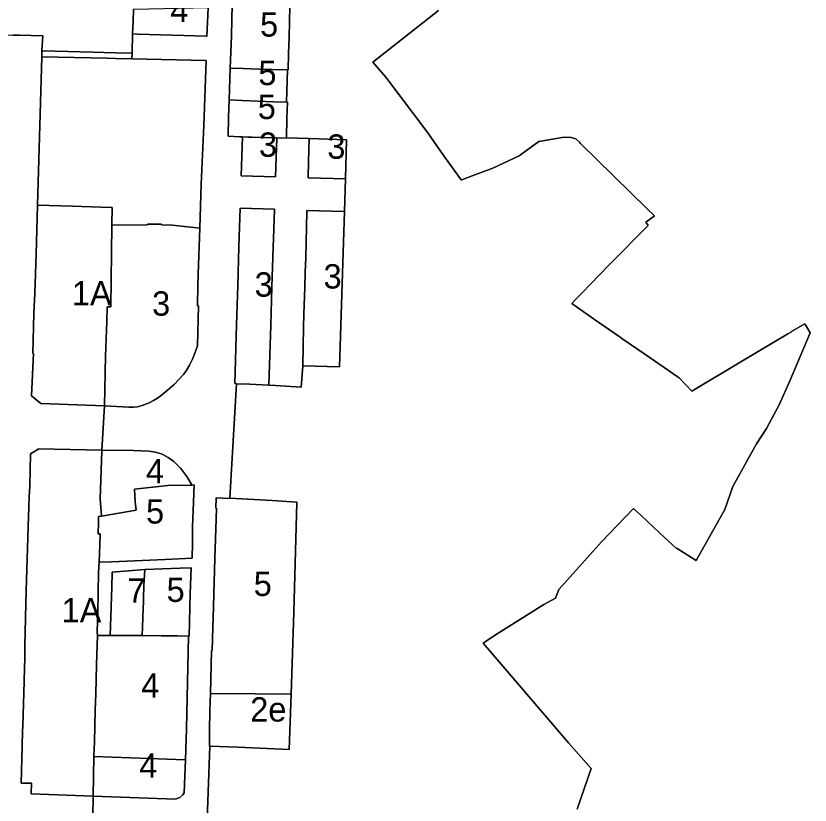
# Model space of a CAD drawing. Extents: x 598968 to 613553, y 4409678 to 4430833.
# Drawn here: x 607609.6 to 608001, y 4414884.2 to 4415273.1 of the extents above; entities that cross this region are included whole.
import ezdxf

# ---------------------------------------------------------------- set-up
doc = ezdxf.new("R2010")
doc.units = 0
for name, color, linetype in [('1', 7, 'Continuous'), ('SUBZONA 2e. CARRERS DE CASES. amb projecte especial', 7, 'Continuous'), ('Sòl Rústic Comú', 7, 'Continuous'), ('ZONA 1A. Cases aïllades extensives - ANNEX III C', 7, 'Continuous'), ("ZONA 3. ILLES  D'EDIFICIS ENTRE MITGERES. EIXAMPLE.", 7, 'Continuous'), ('ZONA 4. CASES UNIFAMILIRAS AÏLLADES EN PARCEL.LES', 7, 'Continuous'), ('ZONA 5. CASES UNIFAMILIARS EN RENGLE', 7, 'Continuous'), ('ZONA 7. CONJUNTS AMB ORDENACIONS ESPECÍFIQUES', 7, 'Continuous')]:
    doc.layers.add(name, color=color, linetype=linetype)

msp = doc.modelspace()

# ---------------------------------------------------------------- linework, layer by layer
at = {"layer": '1'}
for points in [[(607410.898, 4415278.9685), (607410.5229, 4415270.0186), (607420.1369, 4415269.7206), (607442.4766, 4415269.0382), (607474.0118, 4415268.0475), (607551.2448, 4415265.534), (607582.1741, 4415264.3951), (607587.4797, 4415264.2428), (607594.2184, 4415264.0432), (607608.0558, 4415263.6576), (607611.3336, 4415263.5804), (607622.943, 4415263.3067), (607622.3131, 4415255.9868), (607622.8407, 4415255.9718), (607622.8617, 4415255.9712), (607647.4966, 4415255.2678), (607658.7094, 4415254.9477), (607666.8208, 4415254.7342), (607667.1204, 4415264.2254), (607667.3182, 4415270.4899), (607667.4999, 4415276.2469)], [(607704.2805, 4415277.1346), (607703.7565, 4415263.0431), (607703.6158, 4415263.0477), (607669.5537, 4415264.1433), (607667.4355, 4415264.2114), (607667.1204, 4415264.2254), (607666.8208, 4415254.7342), (607666.7335, 4415251.9687), (607703.3718, 4415251.1463), (607703.3689, 4415251.0658), (607702.2186, 4415219.1488), (607700.9421, 4415190.127), (607700.2521, 4415168.5572), (607699.421, 4415145.8761), (607699.3295, 4415140.3856), (607699.1605, 4415130.2392), (607699.6109, 4415130.2271), (607699.0712, 4415110.4665), (607697.7012, 4415106.9366), (607696.5712, 4415103.8766), (607695.2012, 4415100.9666), (607693.5413, 4415098.2266), (607692.1613, 4415096.4366), (607689.9413, 4415093.8866), (607687.5614, 4415091.4866), (607685.3514, 4415089.5465), (607681.3515, 4415086.2065), (607679.4215, 4415084.7665), (607677.3715, 4415083.4965), (607675.2215, 4415082.3964), (607671.8516, 4415081.1064), (607669.5216, 4415080.4764), (607667.5016, 4415080.2263), (607665.2417, 4415080.2263), (607653.2018, 4415081.026), (607652.0336, 4415059.042), (607652.2719, 4415059.0363), (607667.6217, 4415058.8866), (607675.1016, 4415058.5667), (607678.4642, 4415058.1287), (607681.7004, 4415057.1164), (607684.7132, 4415055.5602), (607687.4118, 4415053.507), (607690.8055, 4415050.0328), (607693.7594, 4415046.1778), (607696.2314, 4415041.9973), (607696.2825, 4415041.9277), (607697.3714, 4415041.9473), (607696.8835, 4415029.4088), (607696.6721, 4415021.5497), (607696.6115, 4415013.3976), (607696.4315, 4415005.8577), (607683.2217, 4415005.2475), (607656.672, 4415004.127), (607650.6715, 4415003.9332), (607650.3571, 4414998.8437), (607650.0372, 4414979.1639), (607649.6772, 4414969.604), (607649.8172, 4414967.704), (607649.8167, 4414967.6873), (607656.042, 4414967.6938), (607656.0423, 4414967.7016), (607656.8621, 4414991.5172), (607657.102, 4414998.9871), (607673.1518, 4415000.2574), (607690.6316, 4415001.0077), (607695.9516, 4415001.1778), (607695.4916, 4414988.4979), (607695.2416, 4414981.498), (607695.1417, 4414974.4381), (607695.0417, 4414967.4582), (607694.6687, 4414967.4633), (607694.4118, 4414952.2083), (607694.0618, 4414937.1385), (607693.7019, 4414921.7687), (607693.2319, 4414906.4988), (607692.462, 4414890.199), (607691.912, 4414889.269), (607690.4181, 4414887.9257), (607688.2721, 4414887.179), (607647.6326, 4414888.5782), (607647.5056, 4414878.3639)], [(607701.4745, 4414809.3111), (607705.1961, 4414913.2615), (607704.9718, 4414913.269), (607704.9617, 4414920.8889), (607705.2517, 4414930.6388), (607705.5217, 4414939.1187), (607706.0116, 4414960.4084), (607706.4016, 4414960.3984), (607706.4416, 4414966.1184), (607706.9515, 4414982.0282), (607707.6914, 4415005.8079), (607708.2713, 4415025.1777), (607708.5213, 4415030.5477), (607708.1511, 4415030.5634), (607708.3613, 4415035.5376), (607715.0453, 4415035.2592), (607715.0552, 4415035.4536), (607718.3906, 4415091.8515), (607717.531, 4415091.8771), (607718.3509, 4415120.9368), (607718.9108, 4415140.1165), (607719.4907, 4415159.4263), (607719.7747, 4415169.0478), (607720.0507, 4415178.3961), (607736.9705, 4415177.7964), (607736.6405, 4415167.8465), (607736.3805, 4415158.9166), (607735.7706, 4415139.5468), (607735.1707, 4415120.4871), (607734.2658, 4415091.3781), (607734.265, 4415091.1029), (607737.4992, 4415090.911), (607750.2312, 4415090.1555), (607750.9341, 4415100.5273), (607750.9206, 4415100.5276), (607751.1105, 4415110.1775), (607751.3605, 4415119.7074), (607751.5305, 4415126.0573), (607751.9004, 4415139.3871), (607752.1604, 4415146.817), (607752.4104, 4415153.817), (607752.6103, 4415161.9169), (607752.7703, 4415168.4868), (607752.9903, 4415177.2767), (607771.4869, 4415176.6487), (607771.9745, 4415192.766), (607753.5602, 4415193.3565), (607753.8102, 4415201.3064), (607754.1701, 4415212.5063), (607754.1743, 4415212.6839), (607742.9452, 4415213.0323), (607742.9403, 4415212.8361), (607738.1203, 4415212.976), (607737.5304, 4415193.8462), (607720.6406, 4415194.3559), (607721.2207, 4415213.4971), (607720.0205, 4415213.5357), (607714.1806, 4415213.8056), (607714.3406, 4415223.2255), (607714.7505, 4415231.7354), (607715.2505, 4415247.3752), (607715.4932, 4415255.1651), (607715.7704, 4415263.445), (607716.0004, 4415270.9949), (607716.2418, 4415278.7576)], [(607744.5992, 4415278.054), (607744.4101, 4415270.1954), (607744.2301, 4415262.5955), (607744.0101, 4415254.4256), (607743.8001, 4415246.4757), (607743.4584, 4415246.4865), (607743.0264, 4415230.6274), (607743.3902, 4415230.6159), (607743.1902, 4415222.706), (607742.9452, 4415213.0323), (607754.1743, 4415212.6839), (607772.5598, 4415212.1134), (607772.5539, 4415211.9168), (607771.9745, 4415192.766), (607771.4869, 4415176.6487), (607771.0302, 4415161.5546), (607769.0506, 4415100.246), (607750.9476, 4415100.7259), (607750.9341, 4415100.5273), (607750.2312, 4415090.1555), (607737.4992, 4415090.911), (607734.265, 4415091.1029), (607724.9421, 4415091.6561), (607718.3906, 4415091.8515), (607715.0552, 4415035.4536), (607735.9299, 4415034.2273), (607748.0703, 4415033.5141), (607748.065, 4415033.321), (607746.5793, 4414979.2596), (607745.1678, 4414938.9252), (607744.2106, 4414911.5732), (607718.9326, 4414912.8011), (607705.1961, 4414913.2615), (607701.4745, 4414809.3111)], [(607886.1694, 4414882.1555), (607893.059, 4414902.1653), (607881.8392, 4414914.9345), (607851.7397, 4414950.1526), (607839.7951, 4414964.0452), (607845.5098, 4414967.8269), (607869.769, 4414983.0624), (607875.4689, 4414986.1926), (607877.1288, 4414990.4026), (607898.2282, 4415013.9528), (607913.8876, 4415030.423), (607914.1597, 4415030.1705), (607914.4319, 4415029.918), (607917.5802, 4415026.9975), (607921.058, 4415023.7779), (607929.1074, 4415016.2638), (607934.9972, 4415010.8742), (607935.2478, 4415010.7179), (607935.4983, 4415010.5616), (607944.807, 4415004.7547), (607946.284, 4415007.2808), (607958.8924, 4415029.8453), (607962.8151, 4415041.1918), (607974.5598, 4415062.3033), (607979.5349, 4415069.7646), (607985.6682, 4415081.5115), (607991.1822, 4415093.6736), (608000.9578, 4415116.8981), (607998.6372, 4415120.8479), (607998.4636, 4415121.1435), (607998.29, 4415121.4389), (607991.7543, 4415117.5047), (607991.743, 4415117.498), (607989.9502, 4415116.4187), (607966.7907, 4415102.6012), (607966.7736, 4415102.591), (607942.7471, 4415088.2127), (607942.6718, 4415088.1676), (607942.5966, 4415088.1226), (607936.503, 4415094.7245), (607935.4825, 4415095.4316), (607920.0639, 4415106.1145), (607908.2588, 4415114.1922), (607907.3761, 4415114.7961), (607894.6884, 4415123.4778), (607883.5005, 4415131.4049), (607885.6648, 4415133.6245), (607888.7831, 4415136.8224), (607892.6303, 4415140.7679), (607901.8297, 4415150.2119), (607921.2365, 4415169.7899), (607920.0265, 4415171.3998), (607924.2164, 4415174.5399), (607920.6537, 4415177.9559), (607887.6706, 4415210.4315), (607887.2421, 4415210.8391), (607885.8766, 4415212.1381), (607885.702, 4415212.3043), (607885.5273, 4415212.4706), (607883.2172, 4415213.1874), (607879.8072, 4415213.4173), (607867.3176, 4415211.197), (607857.5778, 4415204.1568), (607844.6305, 4415198.0748), (607834.4891, 4415194.2554), (607829.3102, 4415192.3971), (607829.1841, 4415192.3519), (607829.0586, 4415192.306), (607821.2437, 4415203.0154), (607818.4827, 4415206.9746), (607812.5688, 4415215.4547), (607798.4462, 4415234.154), (607791.834, 4415242.909), (607785.4192, 4415250.3529), (607817.8787, 4415275.7844)], [(607647.5056, 4414878.3639), (607647.6326, 4414888.5782), (607647.6329, 4414888.5951), (607617.0979, 4414889.7343), (607617.2579, 4414894.9343), (607612.2351, 4414895.0363), (607612.6279, 4414913.074), (607612.9222, 4414920.5737), (607612.9713, 4414923.0142), (607613.6578, 4414945.0536), (607613.7707, 4414952.0363), (607614.0176, 4414956.1117), (607614.0477, 4414962.8234), (607614.7135, 4414990.0066), (607615.7574, 4415026.3527), (607616.0774, 4415036.1726), (607616.4574, 4415041.5025), (607616.7773, 4415057.2523), (607620.9073, 4415059.8124), (607652.0271, 4415059.0591), (607652.0265, 4415059.0422), (607652.0336, 4415059.042), (607653.2018, 4415081.026), (607621.9383, 4415082.0834), (607617.3683, 4415085.8532), (607618.2181, 4415106.7996), (607617.9306, 4415106.8115), (607618.5082, 4415126.4128), (607618.8881, 4415136.3926), (607619.5481, 4415155.7224), (607620.203, 4415179.7971), (607620.2543, 4415179.7963), (607622.3476, 4415252.9649), (607622.3131, 4415255.9868), (607622.943, 4415263.3067), (607611.3336, 4415263.5804), (607608.0558, 4415263.6576)]]:
    msp.add_lwpolyline(points, dxfattribs=at)
for points in [[(607666.8208, 4415254.7342), (607658.7094, 4415254.9477), (607647.4966, 4415255.2678), (607622.8617, 4415255.9712), (607622.8407, 4415255.9718), (607622.3131, 4415255.9868), (607622.3476, 4415252.9649), (607654.397, 4415252.2456), (607658.7098, 4415252.1488), (607666.7335, 4415251.9687)], [(607700.9421, 4415190.127), (607702.2186, 4415219.1488), (607703.3689, 4415251.0658), (607703.3718, 4415251.1463), (607666.7335, 4415251.9687), (607658.7098, 4415252.1488), (607654.397, 4415252.2456), (607622.3476, 4415252.9649), (607620.2543, 4415179.7963), (607620.2954, 4415179.7953), (607637.4851, 4415179.3275), (607651.4027, 4415178.8362), (607656.6842, 4415178.7606), (607656.9826, 4415178.7563), (607656.9818, 4415178.6755), (607656.9125, 4415169.9368), (607656.9867, 4415169.9375), (607674.4324, 4415170.0967), (607674.4224, 4415170.4567), (607681.2624, 4415170.5469), (607681.2746, 4415170.2902), (607681.2801, 4415170.1758), (607681.2812, 4415170.0955), (607686.7923, 4415170.017), (607700.2521, 4415168.5572)]]:
    msp.add_lwpolyline(points, close=True, dxfattribs=at)
at = {"layer": 'SUBZONA 2e. CARRERS DE CASES. amb projecte especial'}
msp.add_lwpolyline([(607745.1678, 4414938.9252), (607727.5114, 4414939.0591), (607705.5217, 4414939.1187), (607705.2517, 4414930.6388), (607704.9617, 4414920.8889), (607704.9718, 4414913.269), (607705.1961, 4414913.2615), (607718.9326, 4414912.8011), (607744.2106, 4414911.5732)], close=True, dxfattribs=at)
at = {"layer": 'Sòl Rústic Comú'}
msp.add_lwpolyline([(607817.8787, 4415275.7844), (607785.4192, 4415250.3529), (607791.834, 4415242.909), (607798.4462, 4415234.154), (607812.5688, 4415215.4547), (607818.4827, 4415206.9746), (607821.2437, 4415203.0154), (607829.0586, 4415192.306), (607829.1841, 4415192.3519), (607829.3102, 4415192.3971), (607834.4891, 4415194.2554), (607844.6305, 4415198.0748), (607857.5778, 4415204.1568), (607867.3176, 4415211.197), (607879.8072, 4415213.4173), (607883.2172, 4415213.1874), (607885.5273, 4415212.4706), (607885.702, 4415212.3043), (607885.8766, 4415212.1381), (607887.2421, 4415210.8391), (607887.6706, 4415210.4315), (607920.6537, 4415177.9559), (607924.2164, 4415174.5399), (607920.0265, 4415171.3998), (607921.2365, 4415169.7899), (607901.8297, 4415150.2119), (607892.6303, 4415140.7679), (607888.7831, 4415136.8224), (607885.6648, 4415133.6245), (607883.5005, 4415131.4049), (607894.6884, 4415123.4778), (607907.3761, 4415114.7961), (607908.2588, 4415114.1922), (607920.0639, 4415106.1145), (607935.4825, 4415095.4316), (607936.503, 4415094.7245), (607942.5966, 4415088.1226), (607942.6718, 4415088.1676), (607942.7471, 4415088.2127), (607966.7736, 4415102.591), (607966.7907, 4415102.6012), (607989.9502, 4415116.4187), (607991.743, 4415117.498), (607991.7543, 4415117.5047), (607998.29, 4415121.4389), (607998.4636, 4415121.1435), (607998.6372, 4415120.8479), (608000.9578, 4415116.8981), (607991.1822, 4415093.6736), (607985.6682, 4415081.5115), (607979.5349, 4415069.7646), (607974.5598, 4415062.3033), (607962.8151, 4415041.1918), (607958.8924, 4415029.8453), (607946.284, 4415007.2808), (607944.807, 4415004.7547), (607935.4983, 4415010.5616), (607935.2478, 4415010.7179), (607934.9972, 4415010.8742), (607929.1074, 4415016.2638), (607921.058, 4415023.7779), (607917.5802, 4415026.9975), (607914.4319, 4415029.918), (607914.1597, 4415030.1705), (607913.8876, 4415030.423), (607898.2282, 4415013.9528), (607877.1288, 4414990.4026), (607875.4689, 4414986.1926), (607869.769, 4414983.0624), (607845.5098, 4414967.8269), (607839.7951, 4414964.0452), (607851.7397, 4414950.1526), (607881.8392, 4414914.9345), (607893.059, 4414902.1653), (607886.1694, 4414882.1555)], dxfattribs=at)
at = {"layer": 'ZONA 1A. Cases aïllades extensives - ANNEX III C'}
for points in [[(607620.2543, 4415179.7963), (607620.203, 4415179.7971), (607619.5481, 4415155.7224), (607618.8881, 4415136.3926), (607618.5082, 4415126.4128), (607617.9306, 4415106.8115), (607618.2181, 4415106.7996), (607617.3683, 4415085.8532), (607621.9383, 4415082.0834), (607653.2018, 4415081.026), (607653.8417, 4415105.4255), (607654.3554, 4415122.5586), (607654.5715, 4415129.7646), (607656.4316, 4415129.7155), (607656.9115, 4415169.855), (607656.9125, 4415169.9368), (607656.9818, 4415178.6755), (607656.9826, 4415178.7563), (607656.6842, 4415178.7606), (607651.4027, 4415178.8362), (607637.4851, 4415179.3275), (607620.2954, 4415179.7953)], [(607652.0265, 4415059.0422), (607652.0271, 4415059.0591), (607620.9073, 4415059.8124), (607616.7773, 4415057.2523), (607616.4574, 4415041.5025), (607616.0774, 4415036.1726), (607615.7574, 4415026.3527), (607614.7135, 4414990.0066), (607614.0477, 4414962.8234), (607614.0176, 4414956.1117), (607613.7707, 4414952.0363), (607613.6578, 4414945.0536), (607612.9713, 4414923.0142), (607612.9222, 4414920.5737), (607612.6279, 4414913.074), (607612.2351, 4414895.0363), (607617.2579, 4414894.9343), (607617.0979, 4414889.7343), (607647.6329, 4414888.5951), (607648.0525, 4414908.078), (607648.2616, 4414915.3481), (607648.4781, 4414923.0348), (607648.7199, 4414931.1639), (607648.9424, 4414938.7976), (607649.3623, 4414953.3975), (607649.8122, 4414967.6873), (607649.8167, 4414967.6873), (607649.8172, 4414967.704), (607649.6772, 4414969.604), (607650.0372, 4414979.1639), (607650.3571, 4414998.8437), (607650.6715, 4415003.9332), (607650.9401, 4415012.4756), (607651.1121, 4415017.9467), (607650.7666, 4415017.9153), (607650.1221, 4415017.8567), (607650.1338, 4415018.226), (607650.2877, 4415023.0723), (607650.392, 4415026.3566), (607650.3965, 4415026.3574), (607651.6923, 4415026.5781), (607651.7422, 4415026.5866), (607651.7419, 4415026.5926), (607651.7318, 4415026.8036), (607651.127, 4415035.1732), (607652.0089, 4415058.5769)]]:
    msp.add_lwpolyline(points, close=True, dxfattribs=at)
at = {"layer": "ZONA 3. ILLES  D'EDIFICIS ENTRE MITGERES. EIXAMPLE."}
for points in [[(607738.1203, 4415212.976), (607726.0405, 4415213.3458), (607723.9044, 4415213.4131), (607721.2207, 4415213.4971), (607720.6406, 4415194.3559), (607737.5304, 4415193.8462)], [(607771.9745, 4415192.766), (607772.5539, 4415211.9168), (607772.5598, 4415212.1134), (607754.1743, 4415212.6839), (607754.1701, 4415212.5063), (607753.8102, 4415201.3064), (607753.5602, 4415193.3565)], [(607734.265, 4415091.1029), (607734.2658, 4415091.3781), (607735.1707, 4415120.4871), (607735.7706, 4415139.5468), (607736.3805, 4415158.9166), (607736.6405, 4415167.8465), (607736.9705, 4415177.7964), (607720.0507, 4415178.3961), (607719.7747, 4415169.0478), (607719.4907, 4415159.4263), (607718.9108, 4415140.1165), (607718.3509, 4415120.9368), (607717.531, 4415091.8771), (607718.3906, 4415091.8515), (607724.9421, 4415091.6561)], [(607771.4869, 4415176.6487), (607752.9903, 4415177.2767), (607752.7703, 4415168.4868), (607752.6103, 4415161.9169), (607752.4104, 4415153.817), (607752.1604, 4415146.817), (607751.9004, 4415139.3871), (607751.5305, 4415126.0573), (607751.3605, 4415119.7074), (607751.1105, 4415110.1775), (607750.9206, 4415100.5276), (607750.9341, 4415100.5273), (607750.9476, 4415100.7259), (607769.0506, 4415100.246), (607771.0302, 4415161.5546)], [(607700.2521, 4415168.5572), (607686.7923, 4415170.017), (607681.2812, 4415170.0955), (607681.2801, 4415170.1758), (607681.2746, 4415170.2902), (607681.2624, 4415170.5469), (607674.4224, 4415170.4567), (607674.4324, 4415170.0967), (607656.9867, 4415169.9375), (607656.9125, 4415169.9368), (607656.9115, 4415169.855), (607656.4316, 4415129.7155), (607654.5715, 4415129.7646), (607654.3554, 4415122.5586), (607653.8417, 4415105.4255), (607653.2018, 4415081.026), (607665.2417, 4415080.2263), (607667.5016, 4415080.2263), (607669.5216, 4415080.4764), (607671.8516, 4415081.1064), (607675.2215, 4415082.3964), (607677.3715, 4415083.4965), (607679.4215, 4415084.7665), (607681.3515, 4415086.2065), (607685.3514, 4415089.5465), (607687.5614, 4415091.4866), (607689.9413, 4415093.8866), (607692.1613, 4415096.4366), (607693.5413, 4415098.2266), (607695.2012, 4415100.9666), (607696.5712, 4415103.8766), (607697.7012, 4415106.9366), (607699.0712, 4415110.4665), (607699.6109, 4415130.2271), (607699.1605, 4415130.2392), (607699.3295, 4415140.3856), (607699.421, 4415145.8761)]]:
    msp.add_lwpolyline(points, close=True, dxfattribs=at)
at = {"layer": 'ZONA 4. CASES UNIFAMILIRAS AÏLLADES EN PARCEL.LES'}
for points in [[(607667.1204, 4415264.2254), (607667.4355, 4415264.2114), (607669.5537, 4415264.1433), (607703.6158, 4415263.0477), (607703.7565, 4415263.0431), (607704.2805, 4415277.1346), (607667.8159, 4415276.2578), (607667.4999, 4415276.2469), (607667.3182, 4415270.4899)], [(607652.0336, 4415059.042), (607652.0265, 4415059.0422), (607652.0089, 4415058.5769), (607651.127, 4415035.1732), (607651.7318, 4415026.8036), (607651.7419, 4415026.5926), (607651.7422, 4415026.5866), (607668.9518, 4415029.5169), (607668.4091, 4415033.6983), (607668.0118, 4415039.8968), (607684.4816, 4415041.7171), (607695.7148, 4415041.9174), (607696.2825, 4415041.9277), (607696.2314, 4415041.9973), (607693.7594, 4415046.1778), (607690.8055, 4415050.0328), (607687.4118, 4415053.507), (607684.7132, 4415055.5602), (607681.7004, 4415057.1164), (607678.4642, 4415058.1287), (607675.1016, 4415058.5667), (607667.6217, 4415058.8866), (607652.2719, 4415059.0363)], [(607694.6687, 4414967.4633), (607689.0518, 4414967.548), (607681.1919, 4414967.6579), (607671.772, 4414967.7377), (607659.5221, 4414967.6975), (607656.042, 4414967.6938), (607649.8167, 4414967.6873), (607649.8122, 4414967.6873), (607649.3623, 4414953.3975), (607648.9424, 4414938.7976), (607648.7199, 4414931.1639), (607648.4781, 4414923.0348), (607648.2616, 4414915.3481), (607648.0525, 4414908.078), (607648.0571, 4414908.0778), (607693.2319, 4414906.4988), (607693.7019, 4414921.7687), (607694.0618, 4414937.1385), (607694.4118, 4414952.2083)], [(607693.2319, 4414906.4988), (607648.0571, 4414908.0778), (607648.0525, 4414908.078), (607647.6329, 4414888.5951), (607647.6326, 4414888.5782), (607688.2721, 4414887.179), (607690.4181, 4414887.9257), (607691.912, 4414889.269), (607692.462, 4414890.199)]]:
    msp.add_lwpolyline(points, close=True, dxfattribs=at)
at = {"layer": 'ZONA 5. CASES UNIFAMILIARS EN RENGLE'}
for points in [[(607716.3084, 4415279.353), (607716.2604, 4415279.3548), (607716.2418, 4415278.7576), (607716.0004, 4415270.9949), (607715.7704, 4415263.445), (607715.4932, 4415255.1651), (607715.2505, 4415247.3752), (607721.5404, 4415247.2053), (607729.4103, 4415246.9454), (607735.8257, 4415246.727), (607743.4584, 4415246.4865), (607743.8001, 4415246.4757), (607744.0101, 4415254.4256), (607744.2301, 4415262.5955), (607744.4101, 4415270.1954), (607744.5992, 4415278.054), (607744.6, 4415278.0854), (607744.3195, 4415278.101), (607738.7169, 4415278.4133), (607734.2002, 4415278.6652), (607727.1532, 4415278.935), (607721.6703, 4415279.1449), (607720.3971, 4415279.1943)], [(607743.4584, 4415246.4865), (607735.8257, 4415246.727), (607729.4103, 4415246.9454), (607721.5404, 4415247.2053), (607715.2505, 4415247.3752), (607714.7505, 4415231.7354), (607721.0305, 4415231.4655), (607736.4603, 4415230.8358), (607743.0264, 4415230.6274)], [(607743.0264, 4415230.6274), (607736.4603, 4415230.8358), (607721.0305, 4415231.4655), (607714.7505, 4415231.7354), (607714.3406, 4415223.2255), (607714.1806, 4415213.8056), (607720.0205, 4415213.5357), (607721.2207, 4415213.4971), (607723.9044, 4415213.4131), (607726.0405, 4415213.3458), (607738.1203, 4415212.976), (607742.9403, 4415212.8361), (607742.9452, 4415213.0323), (607743.1902, 4415222.706), (607743.3902, 4415230.6159)], [(607650.6715, 4415003.9332), (607656.672, 4415004.127), (607683.2217, 4415005.2475), (607696.4315, 4415005.8577), (607696.6115, 4415013.3976), (607696.6721, 4415021.5497), (607696.8835, 4415029.4088), (607697.3714, 4415041.9473), (607696.2825, 4415041.9277), (607695.7148, 4415041.9174), (607684.4816, 4415041.7171), (607668.0118, 4415039.8968), (607668.4091, 4415033.6983), (607668.9518, 4415029.5169), (607651.7422, 4415026.5866), (607651.6923, 4415026.5781), (607650.3965, 4415026.3574), (607650.392, 4415026.3566), (607650.2877, 4415023.0723), (607650.1338, 4415018.226), (607650.1221, 4415017.8567), (607650.7666, 4415017.9153), (607651.1121, 4415017.9467), (607650.9401, 4415012.4756)], [(607715.0552, 4415035.4536), (607715.0453, 4415035.2592), (607708.3613, 4415035.5376), (607708.1511, 4415030.5634), (607708.5213, 4415030.5477), (607708.2713, 4415025.1777), (607707.6914, 4415005.8079), (607706.9515, 4414982.0282), (607706.4416, 4414966.1184), (607706.4016, 4414960.3984), (607706.0116, 4414960.4084), (607705.5217, 4414939.1187), (607727.5114, 4414939.0591), (607745.1678, 4414938.9252), (607746.5793, 4414979.2596), (607748.065, 4415033.321), (607748.0703, 4415033.5141), (607735.9299, 4415034.2273)], [(607694.6687, 4414967.4633), (607695.0417, 4414967.4582), (607695.1417, 4414974.4381), (607695.2416, 4414981.498), (607695.4916, 4414988.4979), (607695.9516, 4415001.1778), (607690.6316, 4415001.0077), (607673.1518, 4415000.2574), (607672.7126, 4414992.2674), (607672.5219, 4414986.3975), (607672.4881, 4414985.2968), (607672.3119, 4414980.0176), (607672.2219, 4414977.8126), (607672.1194, 4414975.0573), (607672.052, 4414973.3177), (607672.002, 4414972.0277), (607671.772, 4414967.7377), (607681.1919, 4414967.6579), (607689.0518, 4414967.548)]]:
    msp.add_lwpolyline(points, close=True, dxfattribs=at)
at = {"layer": 'ZONA 7. CONJUNTS AMB ORDENACIONS ESPECÍFIQUES'}
msp.add_lwpolyline([(607671.772, 4414967.7377), (607672.002, 4414972.0277), (607672.052, 4414973.3177), (607672.1194, 4414975.0573), (607672.2219, 4414977.8126), (607672.3119, 4414980.0176), (607672.4881, 4414985.2968), (607672.5219, 4414986.3975), (607672.7126, 4414992.2674), (607673.1518, 4415000.2574), (607657.102, 4414998.9871), (607656.8621, 4414991.5172), (607656.0423, 4414967.7016), (607656.042, 4414967.6938), (607659.5221, 4414967.6975)], close=True, dxfattribs=at)

# ---------------------------------------------------------------- texts
at = {"layer": 'SUBZONA 2e. CARRERS DE CASES. amb projecte especial'}
msp.add_text('2e', height=12, dxfattribs=at).set_placement((607725.0647, 4414925.3459))
at = {"layer": 'ZONA 1A. Cases aïllades extensives - ANNEX III C'}
for p in [(607637.1754, 4415130.4116), (607632.1311, 4414974.2038)]:
    msp.add_text('1A', height=12, dxfattribs=at).set_placement(p)
at = {"layer": "ZONA 3. ILLES  D'EDIFICIS ENTRE MITGERES. EIXAMPLE."}
for p in [(607729.3804, 4415203.6716), (607763.06, 4415202.725), (607761.2037, 4415138.7613), (607727.2508, 4415134.7495), (607676.727, 4415125.3866)]:
    msp.add_text('3', height=12, dxfattribs=at).set_placement(p)
at = {"layer": 'ZONA 4. CASES UNIFAMILIRAS AÏLLADES EN PARCEL.LES'}
for p in [(607685.7005, 4415270.0888), (607673.7048, 4415042.8144), (607671.3606, 4414937.1183), (607670.4323, 4414897.6285)]:
    msp.add_text('4', height=12, dxfattribs=at).set_placement(p)
at = {"layer": 'ZONA 5. CASES UNIFAMILIARS EN RENGLE'}
for p in [(607729.9252, 4415262.9153), (607729.1044, 4415239.0013), (607728.7854, 4415222.2858), (607673.7467, 4415022.9403), (607726.796, 4414987.2314), (607683.8618, 4414984.318)]:
    msp.add_text('5', height=12, dxfattribs=at).set_placement(p)
at = {"layer": 'ZONA 7. CONJUNTS AMB ORDENACIONS ESPECÍFIQUES'}
msp.add_text('7', height=12, dxfattribs=at).set_placement((607664.5969, 4414983.9756))

doc.saveas('drawing.dxf')
